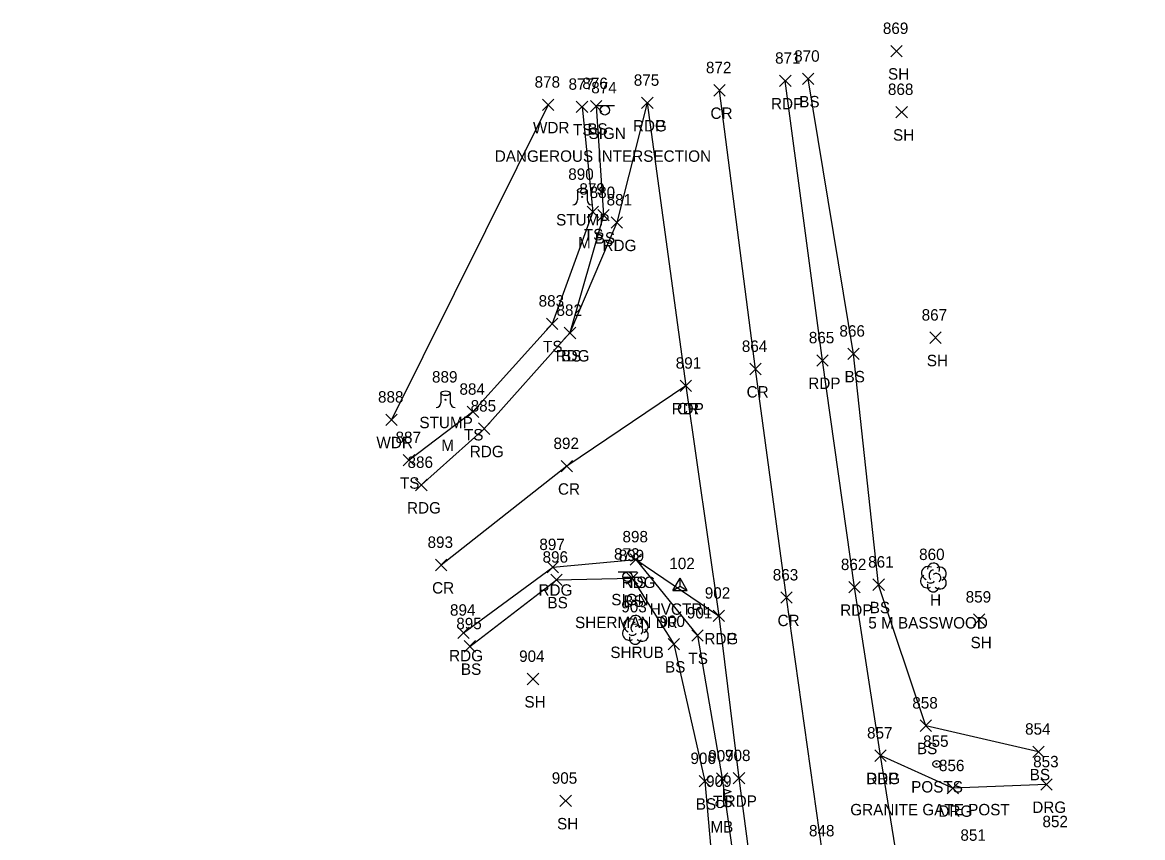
# Model space of a CAD drawing. Extents: x 1629176 to 1637209, y 606063 to 610167.
# Drawn here: x 1629794.4 to 1629990.6, y 607571.9 to 607714.7 of the extents above; entities that cross this region are included whole.
import ezdxf

# ---------------------------------------------------------------- set-up
doc = ezdxf.new("R2010")
doc.units = 0
for name, color, linetype in [('C_A', 7, 'Continuous'), ('C_I', 7, 'Continuous'), ('CPSM', 7, 'Continuous'), ('L_A', 7, 'Continuous'), ('L_C', 7, 'Continuous'), ('L_I', 7, 'Continuous'), ('L_TIC', 7, 'Continuous'), ('LAWA', 7, 'Continuous'), ('LELB', 7, 'Continuous'), ('LMB', 7, 'Continuous'), ('LPST', 7, 'Continuous'), ('LSH', 7, 'Continuous'), ('LTD', 7, 'Continuous'), ('LTS', 7, 'Continuous'), ('P_A', 7, 'Continuous'), ('P_I', 7, 'Continuous'), ('P_TIC', 7, 'Continuous'), ('PET', 7, 'Continuous'), ('PEU', 7, 'Continuous'), ('PRC', 7, 'Continuous'), ('R_A', 7, 'Continuous'), ('R_I', 7, 'Continuous'), ('R_TIC', 7, 'Continuous'), ('RDG', 7, 'Continuous'), ('S_A', 7, 'Continuous'), ('S_C', 7, 'Continuous'), ('S_I', 7, 'Continuous'), ('SSGN', 7, 'Continuous')]:
    doc.layers.add(name, color=color, linetype=linetype)

msp = doc.modelspace()

# ---------------------------------------------------------------- linework, layer by layer
at = {"layer": 'CPSM'}
for p, q in [((1629908.33, 607615.21), (1629909.58, 607617.37)), ((1629910.83, 607615.21), (1629909.58, 607617.37)), ((1629909.58, 607615.93), (1629909.58, 607617.37)), ((1629908.33, 607615.21), (1629909.58, 607615.93)), ((1629908.33, 607615.21), (1629910.83, 607615.21)), ((1629909.58, 607615.93), (1629909.58, 607615.93)), ((1629909.58, 607615.93), (1629910.83, 607615.21))]:
    msp.add_line(p, q, dxfattribs=at)
at = {"layer": 'L_TIC'}
for points in [[(1629946.52, 607708.7), (1629948.52, 607710.7)], [(1629948.52, 607708.7), (1629946.52, 607710.7)], [(1629931.01, 607703.84), (1629933.01, 607705.84)], [(1629933.01, 607703.84), (1629931.01, 607705.84)], [(1629885.45, 607699.29), (1629887.45, 607701.29)], [(1629887.45, 607699.29), (1629885.45, 607701.29)], [(1629891.4, 607698.92), (1629893.4, 607700.92)], [(1629893.4, 607698.92), (1629891.4, 607700.92)], [(1629893.88, 607699.05), (1629895.88, 607701.05)], [(1629895.88, 607699.05), (1629893.88, 607701.05)], [(1629947.4, 607698.01), (1629949.4, 607700.01)], [(1629949.4, 607698.01), (1629947.4, 607700.01)], [(1629893.31, 607680.54), (1629895.31, 607682.54)], [(1629895.31, 607680.54), (1629893.31, 607682.54)], [(1629895.18, 607679.95), (1629897.18, 607681.95)], [(1629897.18, 607679.95), (1629895.18, 607681.95)], [(1629886.16, 607660.93), (1629888.16, 607662.93)], [(1629888.16, 607660.93), (1629886.16, 607662.93)], [(1629889.29, 607659.31), (1629891.29, 607661.31)], [(1629891.29, 607659.31), (1629889.29, 607661.31)], [(1629953.32, 607658.48), (1629955.32, 607660.48)], [(1629955.32, 607658.48), (1629953.32, 607660.48)], [(1629938.96, 607655.66), (1629940.96, 607657.66)], [(1629940.96, 607655.66), (1629938.96, 607657.66)], [(1629872.3, 607645.48), (1629874.3, 607647.48)], [(1629874.3, 607645.48), (1629872.3, 607647.48)], [(1629858.02, 607644.11), (1629860.02, 607646.11)], [(1629860.02, 607644.11), (1629858.02, 607646.11)], [(1629861.09, 607637.02), (1629863.09, 607639.02)], [(1629863.09, 607637.02), (1629861.09, 607639.02)], [(1629900.85, 607619.62), (1629902.85, 607621.62)], [(1629902.85, 607619.62), (1629900.85, 607621.62)], [(1629886.91, 607616.06), (1629888.91, 607618.06)], [(1629888.91, 607616.06), (1629886.91, 607618.06)], [(1629900.2, 607616.32), (1629902.2, 607618.32)], [(1629902.2, 607616.32), (1629900.2, 607618.32)], [(1629943.37, 607615.2), (1629945.37, 607617.2)], [(1629945.37, 607615.2), (1629943.37, 607617.2)], [(1629960.99, 607609.07), (1629962.99, 607611.07)], [(1629962.99, 607609.07), (1629960.99, 607611.07)], [(1629911.64, 607606.29), (1629913.64, 607608.29)], [(1629913.64, 607606.29), (1629911.64, 607608.29)], [(1629871.74, 607604.4), (1629873.74, 607606.4)], [(1629873.74, 607604.4), (1629871.74, 607606.4)], [(1629907.5, 607604.8), (1629909.5, 607606.8)], [(1629909.5, 607604.8), (1629907.5, 607606.8)], [(1629882.82, 607598.68), (1629884.82, 607600.68)], [(1629884.82, 607598.68), (1629882.82, 607600.68)], [(1629951.64, 607590.5), (1629953.64, 607592.5)], [(1629953.64, 607590.5), (1629951.64, 607592.5)], [(1629971.4, 607585.93), (1629973.4, 607587.93)], [(1629973.4, 607585.93), (1629971.4, 607587.93)], [(1629912.9, 607580.78), (1629914.9, 607582.78)], [(1629914.9, 607580.78), (1629912.9, 607582.78)], [(1629915.95, 607581.23), (1629917.95, 607583.23)], [(1629917.95, 607581.23), (1629915.95, 607583.23)], [(1629888.54, 607577.33), (1629890.54, 607579.33)], [(1629890.54, 607577.33), (1629888.54, 607579.33)]]:
    msp.add_lwpolyline(points, dxfattribs=at)
at = {"layer": 'LAWA'}
msp.add_lwpolyline([(1629886.45, 607700.29), (1629859.02, 607645.11)], dxfattribs=at)
at = {"layer": 'LELB'}
for points in [[(1629972.4, 607586.93), (1629952.64, 607591.5), (1629944.37, 607616.2), (1629939.96, 607656.66), (1629932.01, 607704.84)], [(1629892.4, 607699.92), (1629894.31, 607681.54), (1629887.16, 607661.93), (1629873.3, 607646.48), (1629862.09, 607638.02)], [(1629894.88, 607700.05), (1629896.18, 607680.95), (1629890.29, 607660.31)], [(1629901.85, 607620.62), (1629912.64, 607607.29), (1629916.95, 607582.23), (1629921.84, 607547.23), (1629926.69, 607509.97), (1629926.47, 607496.41), (1629932.23, 607463.67), (1629936.65, 607426.68), (1629941.88, 607383.65), (1629948.66, 607331.72), (1629951.48, 607294.54)], [(1629872.74, 607605.4), (1629887.91, 607617.06), (1629901.2, 607617.32), (1629908.5, 607605.8), (1629913.9, 607581.78), (1629917.02, 607546.87), (1629916.16, 607509.81), (1629923.16, 607493.27), (1629925.16, 607453.58), (1629924.47, 607424.14), (1629903.61, 607389.66), (1629905.12, 607348.76), (1629905.7, 607299.56), (1629903.23, 607230.04), (1629906.81, 607190.46), (1629918.09, 607128.12), (1629917.39, 607086.84), (1629912.31, 607067.56), (1629894.57, 607057.72), (1629861.26, 607071.43), (1629823.99, 607082.84), (1629794.36, 607095.25), (1629802.79, 607128.03), (1629840.82, 607119.34)]]:
    msp.add_lwpolyline(points, dxfattribs=at)
at = {"layer": 'LMB'}
for p, q in [((1629917.24, 607580.38), (1629918.53, 607579.99)), ((1629917.24, 607577.78), (1629917.24, 607580.38)), ((1629917.24, 607579.48), (1629918.52, 607579.98)), ((1629916.59, 607577.78), (1629916.59, 607577.78))]:
    msp.add_line(p, q, dxfattribs=at)
msp.add_circle((1629916.59, 607577.78), 0.656, dxfattribs=at)
at = {"layer": 'LPST'}
for radius in [0.625, 0.0833]:
    msp.add_circle((1629954.52, 607584.79), radius, dxfattribs=at)
at = {"layer": 'LSH'}
msp.add_line((1629901.74, 607608.35), (1629901.74, 607608.35), dxfattribs=at)
msp.add_line((1629901.74, 607608.35), (1629901.74, 607608.35), dxfattribs=at)
msp.add_arc((1629901.78, 607609.78), 1.05, 335.5272, 180.9563, dxfattribs=at)
for centre, major_axis, ratio, start_param, end_param in [((1629900.94, 607609.01), (1.21, -0.51), 0.895232, 1.570796, 4.712389), ((1629901.53, 607608.8), (-0.208, -0.792), 0.645439, 3.141593, 6.283185), ((1629902.78, 607608.93), (-1.14, -0.48), 0.949671, 1.570796, 4.712389), ((1629900.65, 607607.64), (0.58, -1.04), 0.959034, 3.141593, 6.283185), ((1629901.28, 607607.6), (-0.625, -0.083), 0.423636, 0, 3.141593), ((1629902.24, 607608.18), (-0.5, 0.667), 0.989748, 3.141593, 6.283185), ((1629902.74, 607607.51), (-1.09, 0.79), 0.841452, 1.570796, 4.712389), ((1629901.74, 607606.85), (0.26, 1.06), 0.942809, 1.570796, 4.712389)]:
    msp.add_ellipse(centre, major_axis=major_axis, ratio=ratio, start_param=start_param, end_param=end_param, dxfattribs=at)
at = {"layer": 'LTD'}
msp.add_line((1629953.95, 607617.52), (1629953.95, 607617.52), dxfattribs=at)
msp.add_line((1629953.95, 607617.52), (1629953.95, 607617.52), dxfattribs=at)
msp.add_arc((1629954, 607618.95), 1.05, 335.5272, 180.9563, dxfattribs=at)
for centre, major_axis, ratio, start_param, end_param in [((1629953.16, 607618.18), (1.21, -0.51), 0.895232, 1.570796, 4.712389), ((1629955, 607618.1), (-1.14, -0.48), 0.949671, 1.570796, 4.712389), ((1629952.87, 607616.81), (0.58, -1.04), 0.959034, 3.141593, 6.283185), ((1629953.75, 607617.97), (-0.208, -0.792), 0.645439, 3.141593, 6.283185), ((1629954.45, 607617.35), (-0.5, 0.667), 0.989748, 3.141593, 6.283185), ((1629954.95, 607616.68), (-1.09, 0.79), 0.841452, 1.570796, 4.712389), ((1629953.95, 607616.02), (0.26, 1.06), 0.942809, 1.570796, 4.712389), ((1629953.5, 607616.77), (-0.625, -0.083), 0.423636, 0, 3.141593)]:
    msp.add_ellipse(centre, major_axis=major_axis, ratio=ratio, start_param=start_param, end_param=end_param, dxfattribs=at)
at = {"layer": 'LTS'}
for p, q in [((1629891.61, 607685.28), (1629891.61, 607683.61)), ((1629892.44, 607684.14), (1629892.44, 607684.14)), ((1629892.44, 607684.14), (1629892.44, 607684.14)), ((1629892.44, 607684.11), (1629892.44, 607684.11)), ((1629893.28, 607685.11), (1629893.28, 607685.28)), ((1629893.28, 607685.28), (1629893.28, 607683.61)), ((1629867.66, 607649.75), (1629867.66, 607648.09)), ((1629868.49, 607648.61), (1629868.49, 607648.61)), ((1629868.49, 607648.61), (1629868.49, 607648.61)), ((1629868.49, 607648.59), (1629868.49, 607648.59)), ((1629869.33, 607649.59), (1629869.33, 607649.75)), ((1629869.33, 607649.75), (1629869.33, 607648.09))]:
    msp.add_line(p, q, dxfattribs=at)
for centre in [(1629892.44, 607684.14), (1629868.49, 607648.61)]:
    msp.add_circle(centre, 0.0833, dxfattribs=at)
for centre, start, end in [((1629890.78, 607683.61), 270, 360), ((1629894.11, 607683.61), 180, 270), ((1629866.83, 607648.09), 270, 360), ((1629870.16, 607648.09), 180, 270)]:
    msp.add_arc(centre, 0.833, start, end, dxfattribs=at)
for centre in [(1629892.44, 607685.28), (1629868.49, 607649.75)]:
    msp.add_ellipse(centre, major_axis=(-0.833, 0), ratio=0.5, dxfattribs=at)
at = {"layer": 'P_TIC'}
for points in [[(1629927.02, 607703.49), (1629929.02, 607705.49)], [(1629929.02, 607703.49), (1629927.02, 607705.49)], [(1629915.48, 607701.82), (1629917.48, 607703.82)], [(1629917.48, 607701.82), (1629915.48, 607703.82)], [(1629902.84, 607699.62), (1629904.84, 607701.62)], [(1629904.84, 607699.62), (1629902.84, 607701.62)], [(1629902.84, 607699.62), (1629904.84, 607701.62)], [(1629904.84, 607699.62), (1629902.84, 607701.62)], [(1629897.5, 607678.65), (1629899.5, 607680.65)], [(1629899.5, 607678.65), (1629897.5, 607680.65)], [(1629889.29, 607659.31), (1629891.29, 607661.31)], [(1629891.29, 607659.31), (1629889.29, 607661.31)], [(1629933.55, 607654.5), (1629935.55, 607656.5)], [(1629935.55, 607654.5), (1629933.55, 607656.5)], [(1629921.81, 607652.99), (1629923.81, 607654.99)], [(1629923.81, 607652.99), (1629921.81, 607654.99)], [(1629909.61, 607650.05), (1629911.61, 607652.05)], [(1629911.61, 607650.05), (1629909.61, 607652.05)], [(1629909.61, 607650.05), (1629911.61, 607652.05)], [(1629911.61, 607650.05), (1629909.61, 607652.05)], [(1629874.25, 607642.54), (1629876.25, 607644.54)], [(1629876.25, 607642.54), (1629874.25, 607644.54)], [(1629888.76, 607635.97), (1629890.76, 607637.97)], [(1629890.76, 607635.97), (1629888.76, 607637.97)], [(1629863.25, 607632.67), (1629865.25, 607634.67)], [(1629865.25, 607632.67), (1629863.25, 607634.67)], [(1629900.85, 607619.62), (1629902.85, 607621.62)], [(1629902.85, 607619.62), (1629900.85, 607621.62)], [(1629866.71, 607618.65), (1629868.71, 607620.65)], [(1629868.71, 607618.65), (1629866.71, 607620.65)], [(1629886.3, 607618.27), (1629888.3, 607620.27)], [(1629888.3, 607618.27), (1629886.3, 607620.27)], [(1629939.16, 607614.76), (1629941.16, 607616.76)], [(1629941.16, 607614.76), (1629939.16, 607616.76)], [(1629927.23, 607612.94), (1629929.23, 607614.94)], [(1629929.23, 607612.94), (1629927.23, 607614.94)], [(1629915.36, 607609.75), (1629917.36, 607611.75)], [(1629917.36, 607609.75), (1629915.36, 607611.75)], [(1629915.36, 607609.75), (1629917.36, 607611.75)], [(1629917.36, 607609.75), (1629915.36, 607611.75)], [(1629870.63, 607606.77), (1629872.63, 607608.77)], [(1629872.63, 607606.77), (1629870.63, 607608.77)], [(1629943.71, 607585.25), (1629945.71, 607587.25)], [(1629945.71, 607585.25), (1629943.71, 607587.25)], [(1629918.9, 607581.29), (1629920.9, 607583.29)], [(1629920.9, 607581.29), (1629918.9, 607583.29)]]:
    msp.add_lwpolyline(points, dxfattribs=at)
at = {"layer": 'PET'}
for points in [[(1629979.67, 607327.82), (1629973.81, 607373.57), (1629968.79, 607410.79), (1629963.89, 607447.44), (1629958.35, 607485.82), (1629952.57, 607527.42), (1629949.09, 607558.98), (1629944.71, 607586.25), (1629940.16, 607615.76), (1629934.55, 607655.5), (1629928.02, 607704.49)], [(1629903.84, 607700.62), (1629910.61, 607651.05), (1629916.36, 607610.75), (1629919.9, 607582.29), (1629924.47, 607547.4), (1629929.48, 607509.85), (1629935.58, 607464.89), (1629940.69, 607427.92), (1629946.3, 607384.48), (1629952.98, 607332.78)]]:
    msp.add_lwpolyline(points, dxfattribs=at)
at = {"layer": 'PEU'}
for points in [[(1629903.84, 607700.62), (1629898.5, 607679.65), (1629890.29, 607660.31), (1629875.25, 607643.54), (1629864.25, 607633.67)], [(1629871.63, 607607.77), (1629887.3, 607619.27), (1629901.85, 607620.62), (1629916.36, 607610.75)]]:
    msp.add_lwpolyline(points, dxfattribs=at)
at = {"layer": 'PRC'}
for points in [[(1629963.88, 606969.73), (1629972.76, 606997.52), (1629981.25, 607028.09), (1629988.12, 607066.47), (1629990.62, 607100.29), (1629990.61, 607124.69), (1629989.69, 607149.78), (1629986.77, 607182.68), (1629981.28, 607228.24), (1629975.13, 607276.5), (1629968.07, 607326.63), (1629961.78, 607372.25), (1629956.91, 607408.66), (1629951.88, 607446.34), (1629946.39, 607483.34), (1629940.59, 607526.71), (1629934.53, 607569.1), (1629928.23, 607613.94), (1629922.81, 607653.99), (1629916.48, 607702.82)], [(1629910.61, 607651.05), (1629889.76, 607636.97), (1629867.71, 607619.65)]]:
    msp.add_lwpolyline(points, dxfattribs=at)
at = {"layer": 'R_TIC'}
for points in [[(1629943.71, 607585.25), (1629945.71, 607587.25)], [(1629945.71, 607585.25), (1629943.71, 607587.25)], [(1629972.8, 607580.21), (1629974.8, 607582.21)], [(1629974.8, 607580.21), (1629972.8, 607582.21)], [(1629956.35, 607579.53), (1629958.35, 607581.53)], [(1629958.35, 607579.53), (1629956.35, 607581.53)]]:
    msp.add_lwpolyline(points, dxfattribs=at)
at = {"layer": 'RDG'}
msp.add_lwpolyline([(1629973.8, 607581.21), (1629957.35, 607580.53), (1629944.71, 607586.25)], dxfattribs=at)
at = {"layer": 'SSGN'}
for p, q in [((1629894.76, 607700.16), (1629898.09, 607700.16)), ((1629896.4, 607699.33), (1629896.4, 607699.33)), ((1629898.74, 607618.44), (1629902.08, 607618.44)), ((1629900.39, 607617.61), (1629900.39, 607617.61))]:
    msp.add_line(p, q, dxfattribs=at)
for centre in [(1629896.4, 607699.33), (1629900.39, 607617.61)]:
    msp.add_circle(centre, 0.833, dxfattribs=at)

# ---------------------------------------------------------------- texts
at = {"layer": 'C_A'}
msp.add_text('HVCTRL', height=2, dxfattribs=at).set_placement((1629904.27, 607610.93))
at = {"layer": 'C_I'}
msp.add_text('102', height=2, dxfattribs=at).set_placement((1629907.7, 607618.93))
at = {"layer": 'L_A'}
for s, p in [('SH', (1629946.01, 607704.7)), ('BS', (1629930.46, 607699.84)), ('WDR', (1629883.81, 607695.29)), ('TS', (1629890.81, 607694.92)), ('BS', (1629893.32, 607695.05)), ('SH', (1629946.89, 607694.01)), ('STUMP', (1629887.86, 607679.14)), ('TS', (1629892.72, 607676.54)), ('BS', (1629894.62, 607675.95)), ('TS', (1629885.57, 607656.93)), ('BS', (1629888.73, 607655.31)), ('SH', (1629952.81, 607654.48)), ('BS', (1629938.4, 607651.66)), ('STUMP', (1629863.91, 607643.62)), ('TS', (1629871.71, 607641.48)), ('WDR', (1629856.38, 607640.11)), ('TS', (1629860.5, 607633.02)), ('TS', (1629900.26, 607615.62)), ('BS', (1629886.35, 607612.06)), ('BS', (1629899.65, 607612.32)), ('BS', (1629942.81, 607611.2)), ('H', (1629953.39, 607612.52)), ('SHRUB', (1629897.37, 607603.35)), ('SH', (1629960.48, 607605.07)), ('TS', (1629911.05, 607602.29)), ('BS', (1629871.18, 607600.4)), ('BS', (1629906.94, 607600.8)), ('SH', (1629882.31, 607594.68)), ('BS', (1629951.08, 607586.5)), ('BS', (1629970.84, 607581.93)), ('POSTS', (1629950.07, 607579.79)), ('BS', (1629912.34, 607576.78)), ('TS', (1629915.36, 607577.23)), ('SH', (1629888.03, 607573.33)), ('MB', (1629914.89, 607572.78))]:
    msp.add_text(s, height=2, dxfattribs=at).set_placement(p)
at = {"layer": 'L_C'}
for s, p in [('M', (1629891.7, 607675.14)), ('M', (1629867.75, 607639.62)), ('5 M BASSWOOD', (1629942.56, 607608.52)), ('GRANITE GATE POST', (1629939.4, 607575.79))]:
    msp.add_text(s, height=2, dxfattribs=at).set_placement(p)
at = {"layer": 'L_I'}
for s, p in [('869', (1629945.11, 607712.7)), ('870', (1629929.57, 607707.84)), ('878', (1629884.09, 607703.29)), ('877', (1629890.04, 607702.92)), ('876', (1629892.46, 607703.05)), ('868', (1629946, 607702.01)), ('890', (1629889.99, 607687.14)), ('879', (1629891.94, 607684.54)), ('880', (1629893.74, 607683.95)), ('883', (1629884.8, 607664.93)), ('882', (1629887.93, 607663.31)), ('867', (1629951.91, 607662.48)), ('866', (1629937.5, 607659.66)), ('889', (1629866.12, 607651.62)), ('884', (1629870.93, 607649.48)), ('888', (1629856.66, 607648.11)), ('887', (1629859.73, 607641.02)), ('898', (1629899.49, 607623.62)), ('896', (1629885.49, 607620.06)), ('899', (1629898.83, 607620.32)), ('861', (1629942.53, 607619.2)), ('860', (1629951.46, 607620.52)), ('859', (1629959.62, 607613.07)), ('903', (1629899.29, 607611.35)), ('901', (1629910.76, 607610.29)), ('895', (1629870.37, 607608.4)), ('900', (1629905.97, 607608.8)), ('904', (1629881.38, 607602.68)), ('858', (1629950.27, 607594.5)), ('854', (1629970.03, 607589.93)), ('855', (1629952.16, 607587.79)), ('906', (1629911.4, 607584.78)), ('907', (1629914.51, 607585.23)), ('905', (1629887.1, 607581.33)), ('909', (1629914.14, 607580.78))]:
    msp.add_text(s, height=2, dxfattribs=at).set_placement(p)
at = {"layer": 'P_A'}
for s, p in [('RDP', (1629925.51, 607699.49)), ('CR', (1629914.91, 607697.82)), ('RDG', (1629901.32, 607695.62)), ('RDP', (1629901.32, 607695.62)), ('RDG', (1629895.99, 607674.65)), ('RDG', (1629887.78, 607655.31)), ('RDP', (1629932.04, 607650.5)), ('CR', (1629921.24, 607648.99)), ('RDP', (1629908.1, 607646.05)), ('CR', (1629909.05, 607646.05)), ('RDG', (1629872.74, 607638.54)), ('CR', (1629888.19, 607631.97)), ('RDG', (1629861.74, 607628.67)), ('RDG', (1629899.34, 607615.62)), ('CR', (1629866.14, 607614.65)), ('RDG', (1629884.78, 607614.27)), ('RDP', (1629937.64, 607610.76)), ('CR', (1629926.66, 607608.94)), ('RDG', (1629913.84, 607605.75)), ('RDP', (1629913.84, 607605.75)), ('RDG', (1629869.12, 607602.77)), ('RDP', (1629942.19, 607581.25)), ('RDP', (1629917.39, 607577.29))]:
    msp.add_text(s, height=2, dxfattribs=at).set_placement(p)
at = {"layer": 'P_I'}
for s, p in [('871', (1629926.23, 607707.49)), ('872', (1629914.11, 607705.82)), ('875', (1629901.47, 607703.62)), ('875', (1629901.47, 607703.62)), ('881', (1629896.71, 607682.65)), ('882', (1629887.93, 607663.31)), ('865', (1629932.14, 607658.5)), ('864', (1629920.4, 607656.99)), ('891', (1629908.82, 607654.05)), ('891', (1629908.82, 607654.05)), ('885', (1629872.89, 607646.54)), ('892', (1629887.4, 607639.97)), ('886', (1629861.83, 607636.67)), ('898', (1629899.49, 607623.62)), ('893', (1629865.34, 607622.65)), ('897', (1629884.93, 607622.27)), ('863', (1629925.82, 607616.94)), ('862', (1629937.75, 607618.76)), ('902', (1629913.91, 607613.75)), ('902', (1629913.91, 607613.75)), ('894', (1629869.27, 607610.77)), ('857', (1629942.34, 607589.25)), ('908', (1629917.46, 607585.29)), ('848', (1629932.17, 607572.1))]:
    msp.add_text(s, height=2, dxfattribs=at).set_placement(p)
at = {"layer": 'R_A'}
for p in [(1629942.19, 607581.25), (1629971.29, 607576.21), (1629954.84, 607575.53)]:
    msp.add_text('DRG', height=2, dxfattribs=at).set_placement(p)
at = {"layer": 'R_I'}
for s, p in [('857', (1629942.34, 607589.25)), ('853', (1629971.44, 607584.21)), ('856', (1629954.94, 607583.53)), ('852', (1629973.07, 607573.71)), ('851', (1629958.7, 607571.33))]:
    msp.add_text(s, height=2, dxfattribs=at).set_placement(p)
at = {"layer": 'S_A'}
for p in [(1629893.54, 607694.3), (1629897.53, 607612.59)]:
    msp.add_text('SIGN', height=2, dxfattribs=at).set_placement(p)
at = {"layer": 'S_C'}
for s, p in [('DANGEROUS INTERSECTION', (1629877.12, 607690.3)), ('SHERMAN DR', (1629891.18, 607608.59))]:
    msp.add_text(s, height=2, dxfattribs=at).set_placement(p)
at = {"layer": 'S_I'}
for s, p in [('874', (1629894.02, 607702.3)), ('873', (1629898.01, 607620.59))]:
    msp.add_text(s, height=2, dxfattribs=at).set_placement(p)

doc.saveas('drawing.dxf')
